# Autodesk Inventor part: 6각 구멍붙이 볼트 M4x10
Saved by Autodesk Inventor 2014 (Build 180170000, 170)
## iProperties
Created: 2026-05
Part Number: 6각 구멍붙이 볼트 M4x10
Material: 일반
Document SubType Name: Modeling
Designer: dg
Density: 1 g/cm^3
Appearance: 기본값
Author: dg
Author: jhkim
Description: 6각머리 태핑 나사
Creation Date: 2026-04-23
Sending System: Autodesk Inventor 2027
Preprocessor: ST-DEVELOPER v20.1
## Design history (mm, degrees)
node "6각 구멍붙이 볼트 M4x101"
body "Solid1"
node "기준1"
